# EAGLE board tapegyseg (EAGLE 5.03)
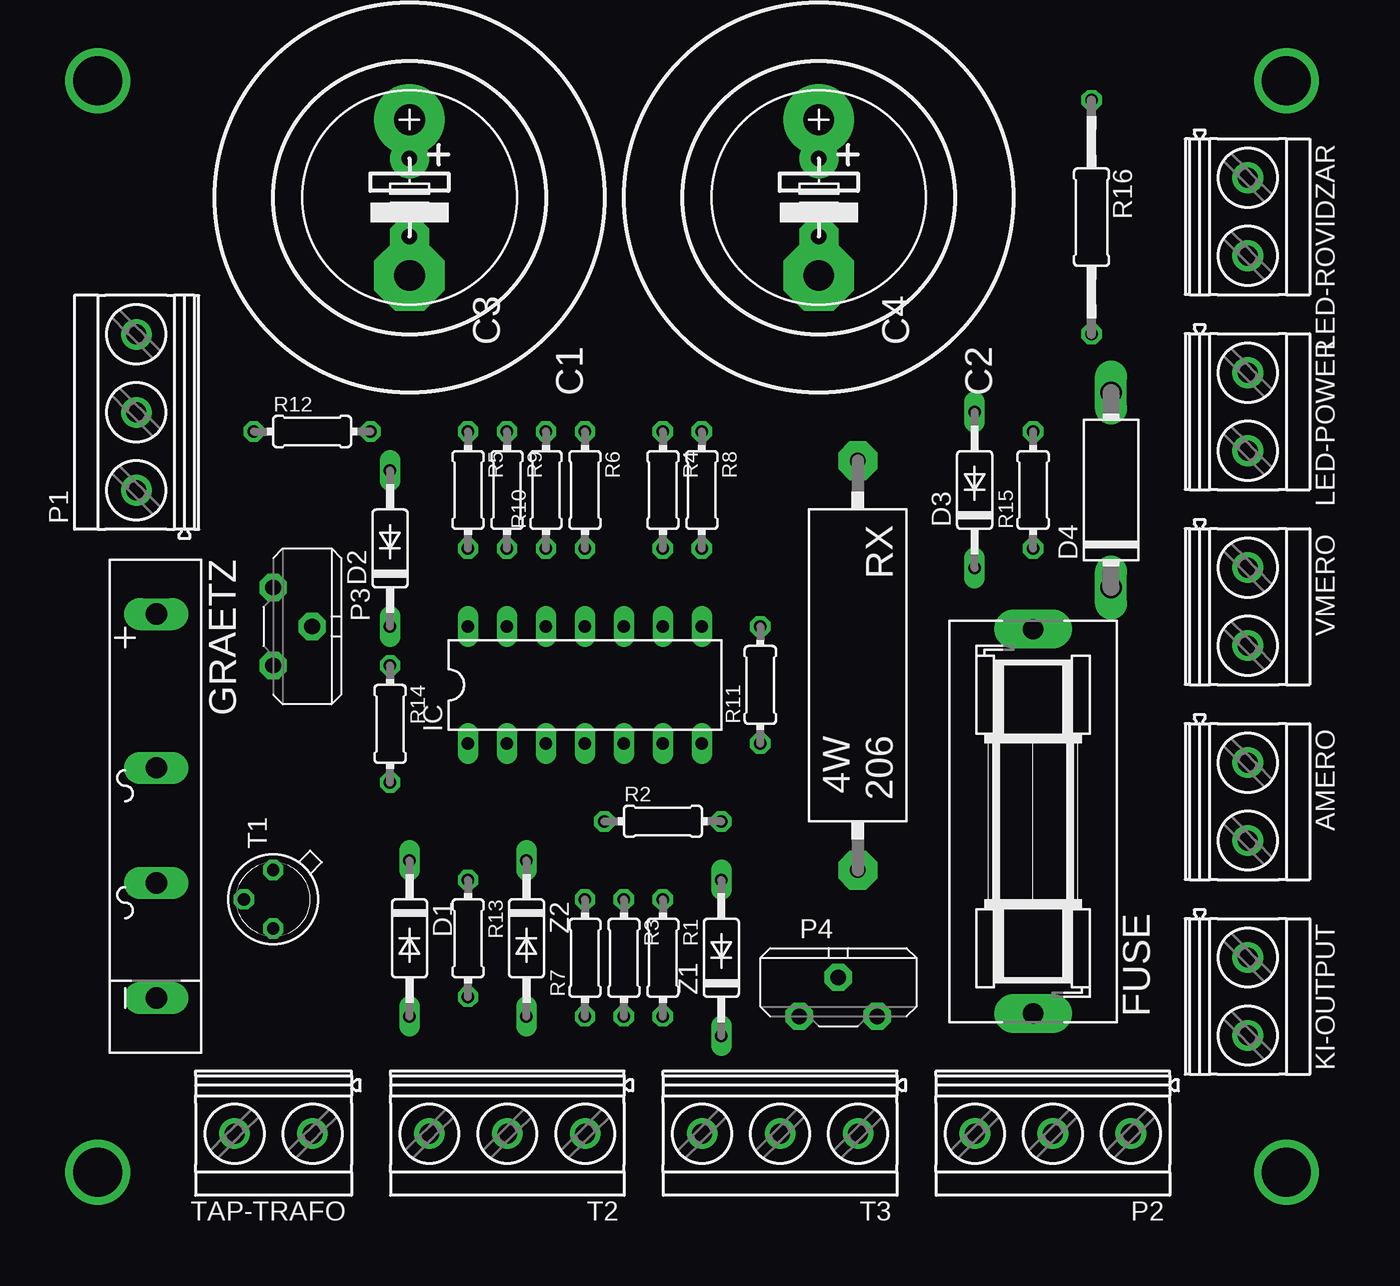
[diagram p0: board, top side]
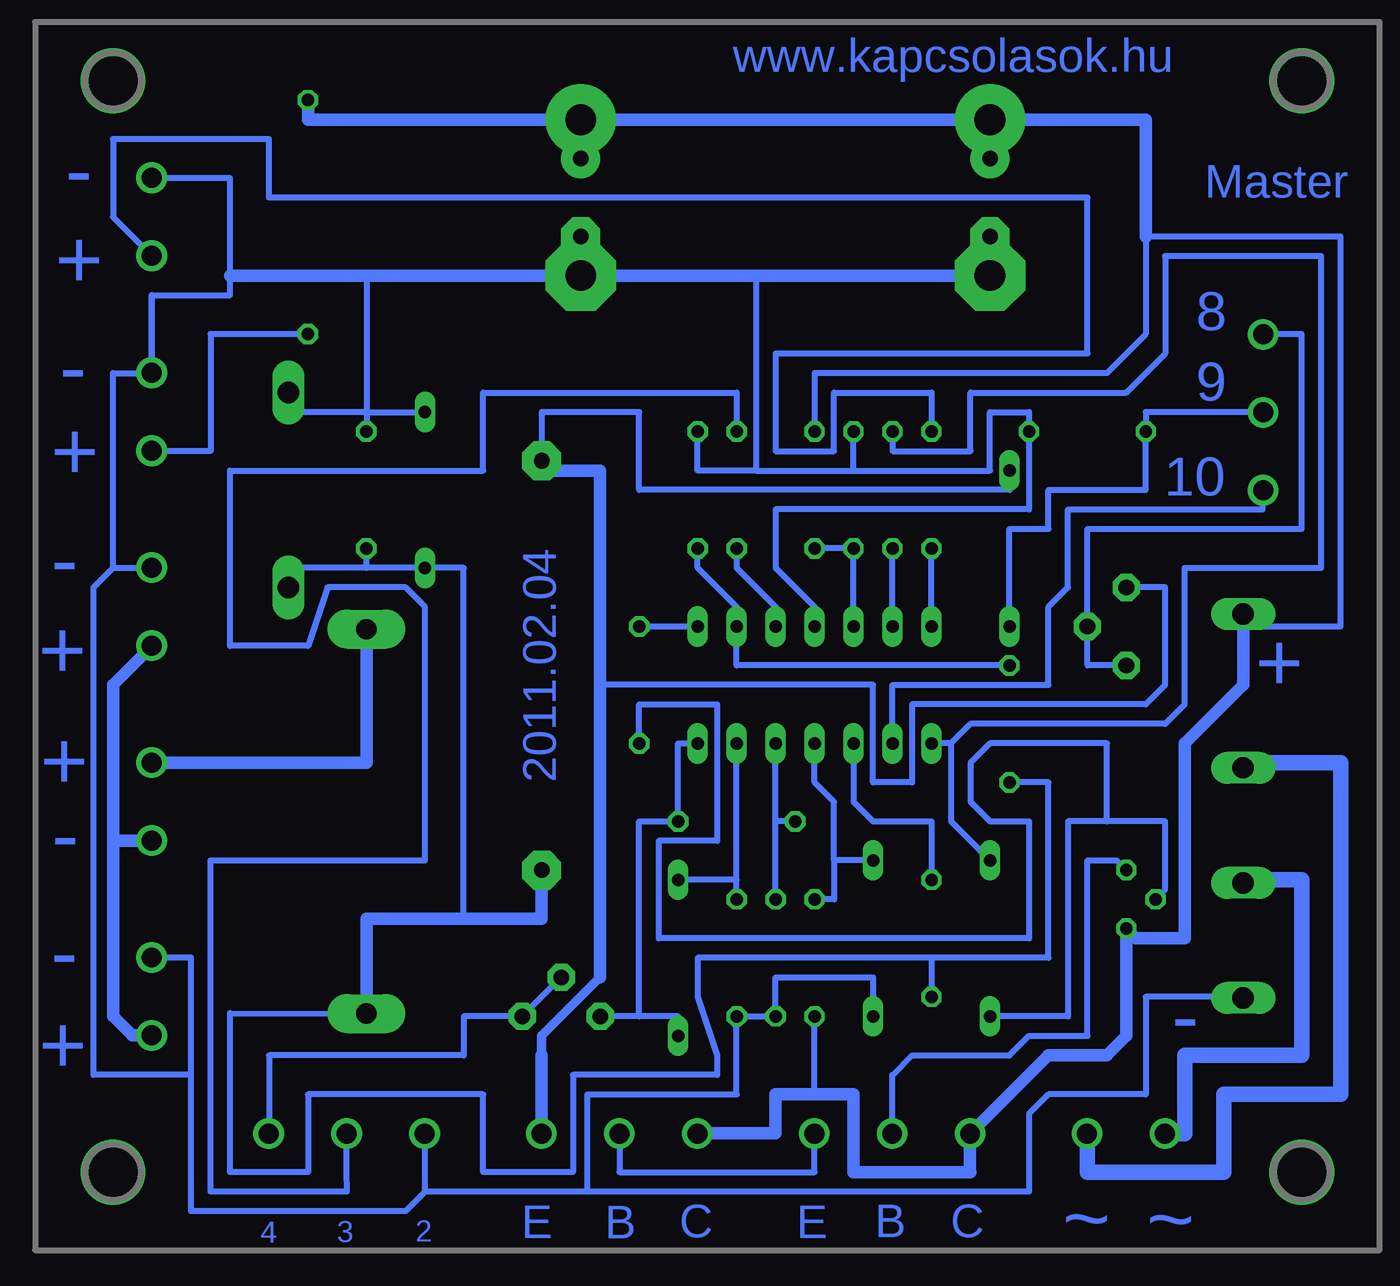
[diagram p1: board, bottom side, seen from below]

No outline drawn. Coordinates in mm, seen from the top.
Copper layers (1*16): Top 0.035mm / dielectric 1.5mm / Bottom 0.035mm
Design rules "default": minimum track width 10mil, minimum drill 24mil, track to track 8mil, track to pad 8mil, pad to pad 8mil, via to via 8mil, smd to smd 8mil, copper to edge 40mil, drill to drill 8mil, minimum pad ring 10mil, minimum via ring 8mil, stop-mask expansion 4mil, vias tented up to drill 0mil, thermal gap 10mil

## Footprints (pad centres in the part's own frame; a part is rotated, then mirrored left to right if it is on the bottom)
MKDSN1,5/2-5,08 = drill 1.3 pad 2 round: 1 -2.561,0.025; 2 2.519,0.025
EB25D = drill 2.007 pad 4.597 round: + -5.08,0 | drill 2.007 pad 4.597 octagon: - 5.08,0
E5-13 = drill 1.016 pad 2.54 round: + -2.54,0 | drill 1.016 pad 2.54 octagon: - 2.54,0
C2992 = drill 0.813 long: A 5.08,0; C -5.08,0
CB417-12 = drill 1.397 long: A 6.35,0; C -6.35,0
SH25 = drill 1.321 pad 2.54 long: 1 -12.522,0; 2 12.522,0
FB32 = drill 1.397 long: + -13.5,0; - 11.494,0; AC1 -3.492,0; AC2 4.001,0
DIL14 = drill 0.813 long: 1 -7.62,-3.81; 2 -5.08,-3.81; 3 -2.54,-3.81; 4 0,-3.81; 5 2.54,-3.81; 6 5.08,-3.81; 7 7.62,-3.81; 8 7.62,3.81; 9 5.08,3.81; 10 2.54,3.81; 11 0,3.81; 12 -2.54,3.81; 13 -5.08,3.81; 14 -7.62,3.81
MKDSN1,5/3-5,08 = drill 1.3 pad 2 round: 1 -7.641,0.025; 2 -2.561,0.025; 3 2.519,0.025
PT-10S = drill 1.016 pad 1.778 octagon: 1 -2.54,-1.27; 2 2.54,-1.27; 3 0,1.27
0204/7 = drill 0.813 octagon: 1 -3.81,0; 2 3.81,0
0207/15 = drill 0.813 octagon: 1 -7.62,0; 2 7.62,0
KH206-8 = drill 1.016 pad 2.54 octagon: 1 -13.335,0; 2 13.335,0
TO18- = drill 0.813 octagon: 1 1.905,0; 2 0,1.905; 3 -1.905,0

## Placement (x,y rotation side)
AMERO  [MKDSN1,5/2-5,08]  80.01,29.21 270 top
C1  [EB25D]  25.4,68.58 270 top
C2  [EB25D]  52.07,68.58 270 top
C3  [E5-13]  25.4,68.58 270 top
C4  [E5-13]  52.07,68.58 270 top
D1  [C2992]  25.4,20.32 270 top
D2  [C2992]  24.13,45.72 90 top
D3  [C2992]  62.23,49.53 90 top
D4  [CB417-12]  71.12,49.53 90 top
FUSE  [SH25]  66.04,27.94 90 top
GRAETZ  [FB32]  8.89,27.94 270 top
IC  [DIL14]  36.83,36.83 0 top
KI-OUTPUT  [MKDSN1,5/2-5,08]  80.01,16.51 270 top
LED-POWER  [MKDSN1,5/2-5,08]  80.01,54.61 270 top
LED-ROVIDZAR  [MKDSN1,5/2-5,08]  80.01,67.31 270 top
P1  [MKDSN1,5/3-5,08]  7.62,57.15 90 top
P2  [MKDSN1,5/3-5,08]  64.77,7.62 180 top
P3  [PT-10S]  17.78,40.64 270 top
P4  [PT-10S]  53.34,16.51 0 top
R1  [0204/7]  41.91,19.05 270 top
R2  [0204/7]  41.91,27.94 0 top
R3  [0204/7]  39.37,19.05 270 top
R4  [0204/7]  41.91,49.53 270 top
R5  [0204/7]  29.21,49.53 270 top
R6  [0204/7]  36.83,49.53 270 top
R7  [0204/7]  36.83,19.05 90 top
R8  [0204/7]  44.45,49.53 270 top
R9  [0204/7]  31.75,49.53 270 top
R10  [0204/7]  34.29,49.53 90 top
R11  [0204/7]  48.26,36.83 90 top
R12  [0204/7]  19.05,53.34 0 top
R13  [0204/7]  29.21,20.32 270 top
R14  [0204/7]  24.13,34.29 270 top
R15  [0204/7]  66.04,49.53 90 top
R16  [0207/15]  69.85,67.31 270 top
RX  5W  [KH206-8]  54.61,38.1 270 top
T1  [TO18-]  16.51,22.86 90 top
T2  [MKDSN1,5/3-5,08]  29.21,7.62 180 top
T3  [MKDSN1,5/3-5,08]  46.99,7.62 180 top
TAP-TRAFO  [MKDSN1,5/2-5,08]  16.51,7.62 180 top
VMERO  [MKDSN1,5/2-5,08]  80.01,41.91 270 top
Z1  [C2992]  45.72,19.05 90 top
Z2  [C2992]  33.02,20.32 270 top

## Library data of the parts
AMERO KI-OUTPUT LED-POWER LED-ROVIDZAR P1 P2 T2 T3 TAP-TRAFO VMERO = con-phoenix-508
C1-C4 P3 P4 R1-R16 = rcl
D1-D4 Z1 Z2 = diode
FUSE = fuse
GRAETZ = rectifier
IC = 40xx
RX = resistor-power
T1 = transistor

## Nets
P4: P2.1 P4.2 P4.3
S$1: GRAETZ.AC2 TAP-TRAFO.2
S$2: GRAETZ.AC1 TAP-TRAFO.1
S$3: C1.+ C2.+ C3.+ C4.+ GRAETZ.+ R6.1 R7.1 R16.1 T1.3 T2.3 T3.3
S$4: C1.- C2.- C3.- C4.- D3.A D4.A GRAETZ.- IC.11 KI-OUTPUT.1 LED-POWER.1 LED-ROVIDZAR.1 P2.3 R1.2 R3.2 R8.1 R10.2 R12.2 R15.2 VMERO.1 Z2.A
S$5: T2.1 T3.2
S$6: T1.1 T2.2
S$7: IC.4 R7.2 Z2.C
S$8: IC.12 R6.2 R10.1
S$9: D1.A R11.1 T1.2
S$10: IC.8 R11.2
S$11: D1.C IC.1 R9.1
S$12: IC.13 R9.2
S$13: IC.7 P4.1 R2.2 Z1.C
S$14: IC.6 R1.1 Z1.A
S$15: IC.5 R2.1 R3.1
S$16: P1.3 P3.2 P3.3
S$17: P2.2 R4.1
S$18: IC.10 R4.2
S$19: LED-ROVIDZAR.2 R5.1
S$20: IC.14 R5.2
S$21: IC.9 R8.2 R14.1
S$22: D3.C D4.C FUSE.1 R13.2 R14.2 R15.1 RX.2
S$23: IC.3 R13.1
S$24: D2.A P3.1 RX.1 T3.1
S$25: D2.C P1.2 R12.1
S$26: IC.2 P1.1
S$27: AMERO.1 FUSE.2
S$28: LED-POWER.2 R16.2
S$29: AMERO.2 KI-OUTPUT.2 VMERO.2

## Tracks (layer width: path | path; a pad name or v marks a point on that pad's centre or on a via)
P4
  Bottom 0.406: P4.3 P4.2 59.69,15.24 59.69,12.7 72.39,12.7 72.39,7.62 P2.1
S$1
  Bottom 1.016: TAP-TRAFO.2 12.7,7.59 12.7,12.7 5.08,12.7 5.08,24.13 7.62,24.13 GRAETZ.AC2
S$2
  Bottom 1.016: TAP-TRAFO.1 19.05,6.33 19.05,5.08 10.16,5.08 10.16,10.16 2.54,10.16 2.54,31.75 8.89,31.75 GRAETZ.AC1
S$3
  Bottom 0.406: R6.1 36.83,57.15 17.78,57.15 15.24,59.69 15.24,66.04 2.54,66.04 2.54,40.64 8.89,40.64 GRAETZ.+ | 36.83,10.16 R7.1 | T2.3 26.67,7.57
  Bottom 0.813: 8.89,40.64 8.89,36.83 12.7,33.02 12.7,20.32 15.88,20.32 T1.3 16.51,13.97 17.78,12.7 21.59,12.7 T2.3 26.69,5.1 26.67,5.08 34.29,5.08 34.29,10.16 36.83,10.16 39.37,10.16 39.37,7.62 44.45,7.62 T3.3 | 15.24,66.04 15.24,73.66 C1.+ | C1.+ C3.+ | C1.+ C2.+ | C2.+ C4.+ | C2.+ 69.85,73.66 R16.1
S$4
  Bottom 0.406: IC.11 36.83,41.91 39.37,44.45 39.37,48.26 22.86,48.26 R12.2 22.86,54.61 25.4,54.61 25.4,50.8 34.29,50.8 | R8.1 44.45,50.8 40.64,50.8 | 34.29,50.8 R10.2 | 40.64,50.8 34.29,50.8 | D4.A 71.12,54.61 66.04,54.61 | 40.64,63.5 40.64,50.8 | LED-ROVIDZAR.1 80.01,69.85 74.93,69.85 74.93,63.5 74.93,62.23 80.01,62.23 | 66.04,54.61 D3.A | 66.04,54.61 R15.2 | 66.04,63.5 66.04,54.61 | 80.01,62.23 80.03,62.2 LED-POWER.1 80.06,57.15 82.55,57.15 | 80.01,62.23 80.01,57.15 82.55,57.15 | VMERO.1 82.53,44.47 82.55,44.45 | 82.55,44.45 82.55,57.15 | Z2.A 33.02,17.78 39.37,17.78 R3.2 R1.2 41.91,10.16 51.63,10.16 51.63,3.81 | KI-OUTPUT.1 77.49,19.07 77.47,19.05 77.47,11.43 | 82.55,44.45 83.82,43.18 83.82,11.43 77.47,11.43 | 77.47,11.43 77.47,2.54 63.5,2.54 62.23,3.81 | P2.3 62.23,7.57 62.23,3.81 | 51.63,3.81 62.23,3.81 | 51.63,3.81 22.86,3.81 22.86,8.89 21.59,10.16 15.24,10.16 15.24,16.51 8.89,16.51 GRAETZ.-
  Bottom 0.813: C2.- 40.64,63.5 C1.- C3.- | C2.- 66.04,63.5 74.93,63.5 | C2.- C4.-
S$5
  Bottom 0.406: T3.2 49.55,5.1 49.53,5.08 36.83,5.08 36.83,7.57 T2.1
S$6
  Bottom 0.406: T2.2 31.77,11.41 30.48,12.7 24.13,12.7 22.86,13.97 19.05,13.97 19.05,25.4 17.14,25.4 T1.1
S$7
  Bottom 0.406: 35.56,25.4 35.56,22.86 R7.2 | 35.56,25.4 35.56,29.21 36.83,30.48 IC.4 | Z2.C 35.56,25.4
S$8
  Bottom 0.406: IC.12 R10.1 R6.2
S$9
  Bottom 0.406: D1.A 20.32,15.24 20.32,27.94 17.78,27.94 | 17.78,27.94 13.97,27.94 13.97,23.5 T1.2 | 17.78,27.94 17.78,33.02 25.4,33.02 26.67,31.75 26.67,29.21 25.4,27.94 22.86,27.94 22.86,20.32 46.99,20.32 46.99,26.67 43.18,26.67 43.18,35.56 48.26,35.56 R11.1
S$10
  Bottom 0.406: R11.2 IC.8
S$11
  Bottom 0.406: 27.94,33.02 27.94,27.94 D1.C | 27.94,33.02 26.67,34.29 13.97,34.29 12.7,35.56 12.7,44.45 3.81,44.45 3.81,64.77 13.97,64.77 13.97,58.42 16.51,55.88 26.67,55.88 26.67,52.07 31.75,52.07 R9.1 | 27.94,33.02 IC.1
S$12
  Bottom 0.406: IC.13 R9.2
S$13
  Bottom 0.406: IC.7 45.72,33.02 R2.2 48.26,27.94 48.26,15.24 | 48.26,15.24 45.72,15.24 Z1.C | 48.26,15.24 P4.1
S$14
  Bottom 0.406: R1.1 41.91,24.13 | 41.91,24.13 IC.6 | 41.91,24.13 Z1.A
S$15
  Bottom 0.406: 39.37,27.94 IC.5 | R2.1 39.37,27.94 | R3.1 39.37,27.94
S$16
  Bottom 0.406: P3.2 19.05,38.1 P3.3 19.05,46.99 5.08,46.99 5.08,59.69 7.57,59.69 P1.3
S$17
  Bottom 0.406: P2.2 67.33,5.1 67.31,3.81 76.2,3.81 76.2,25.4 62.23,25.4 62.23,41.91 63.5,43.18 68.58,43.18 69.85,39.37 74.93,39.37 74.93,50.8 58.42,50.8 58.42,55.88 41.91,55.88 R4.1
S$18
  Bottom 0.406: R4.2 41.91,44.45 39.37,41.91 IC.10
S$19
  Bottom 0.406: LED-ROVIDZAR.2 82.55,67.31 82.55,72.39 72.39,72.39 72.39,68.58 19.05,68.58 19.05,58.42 39.37,58.42 39.37,52.07 35.56,52.07 35.56,55.88 29.21,55.88 R5.1
S$20
  Bottom 0.406: IC.14 R5.2
S$21
  Bottom 0.406: R8.2 44.45,44.45 41.91,41.91 IC.9 41.91,38.1 R14.1
S$22
  Bottom 0.406: 66.04,44.45 D3.C 59.69,44.45 59.69,21.59 | 29.21,19.05 R13.2 | 29.21,19.05 21.59,19.05 21.59,30.48 R14.2 | 29.21,19.05 44.45,19.05 44.45,16.51 43.18,12.7 43.18,11.43 52.58,11.43 52.58,5.08 58.42,5.08 58.42,10.16 69.85,10.16 69.85,5.08 74.93,5.08 74.93,15.44 FUSE.1 | 66.04,44.45 R15.1 | 66.04,44.45 71.12,44.45 D4.C
  Bottom 0.813: RX.2 54.61,21.59 59.69,21.59 66.04,21.59 FUSE.1
S$23
  Bottom 0.406: IC.3 34.29,29.21 33.02,27.94 29.21,27.94 R13.1
S$24
  Bottom 0.406: P3.1 13.97,43.18 13.97,36.83 15.24,35.56 30.48,35.56 30.48,30.48 33.02,30.48 33.02,36.83 50.8,36.83 | D2.A 24.13,49.53 48.26,49.53 48.26,54.61 54.61,54.61 RX.1
  Bottom 0.61: 54.61,12.7 54.61,13.97 50.8,17.78
  Bottom 0.813: T3.1 54.63,12.68 54.61,12.7 | 50.8,17.78 50.8,36.83 50.8,50.8 53.98,50.8 RX.1
S$25
  Bottom 0.406: P1.2 7.59,54.61 15.24,54.61 R12.1 15.24,49.53 21.59,49.53 21.59,46.99 24.13,46.99 D2.C
S$26
  Bottom 0.406: IC.2 31.75,36.83 21.59,36.83 21.59,41.91 20.32,43.18 20.32,48.26 7.62,48.26 7.59,49.53 P1.1
S$27
  Bottom 0.813: FUSE.2 66.04,31.75 80.01,31.75 AMERO.1
S$28
  Bottom 0.406: R16.2 76.2,59.69 76.2,52.07 80.01,52.07 LED-POWER.2
S$29
  Bottom 0.813: VMERO.2 80.03,39.34 82.55,36.83 82.55,26.67 | AMERO.2 82.53,26.69 82.55,26.67 | KI-OUTPUT.2 81.3,13.99 82.55,15.24 82.55,26.67
S$34  (via drill 3.2)
  other vias: 5.08,5.08
S$36  (via drill 3.2)
  other vias: 82.55,5.08
S$39  (via drill 3.2)
  other vias: 82.55,76.2
S$40  (via drill 3.2)
  other vias: 5.08,76.2

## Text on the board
Bottom: www.kapcsolasok.hu | Master | - | + | 8 | - | 9 | + | 10 | 2011.02.04 | - | + | + | + | - | - | - | + | C | B | E | C | B | E | 2 | 3 | ~ | ~ | 4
